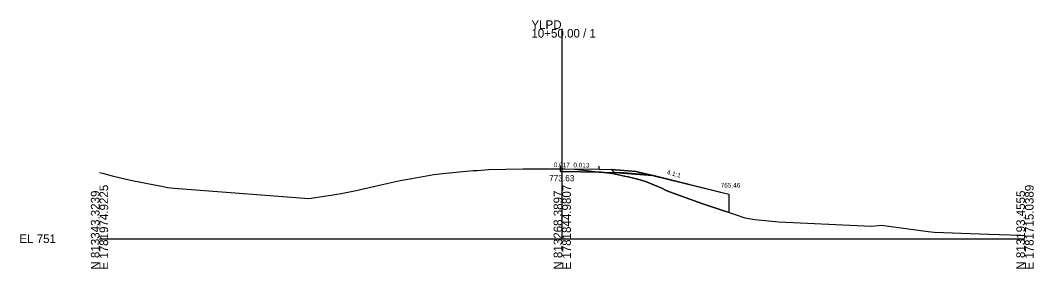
# Model space of a CAD drawing. Extents: x -26 to 353, y -10 to 9080.
# Drawn here: x -25.7 to 302.8, y 490.3 to 570.7 of the extents above; entities that cross this region are included whole.
import ezdxf

# ---------------------------------------------------------------- set-up
doc = ezdxf.new("R2010")
doc.units = 0
for name, color, linetype in [('Exist Cross Section Cell', 7, 'Continuous'), ('Exist XS Center Line Elevation Label', 7, 'Continuous'), ('Exist XS Ground Line', 7, 'Continuous'), ('Prop XS Ditch Standard Text', 7, 'Continuous'), ('Prop XS Dump Level', 7, 'Continuous'), ('Prop XS Earthwork Shape', 7, 'Continuous'), ('Prop XS EOT Tick Mark', 7, 'Continuous'), ('Prop XS Finish Grade', 7, 'Continuous'), ('Prop XS Finish Grade Earthwork', 7, 'Continuous'), ('Prop XS Finish Grade Paved Shoulder', 7, 'Continuous'), ('Prop XS Finish Grade Pavement', 7, 'Continuous'), ('Prop XS Pvmt Edge Slope', 7, 'Continuous'), ('Prop XS SE Text', 7, 'Continuous'), ('Prop XS Side Slope Text', 7, 'Continuous'), ('Prop XS Subgrade Earthwork', 7, 'Continuous'), ('Scratch_Level_3', 7, 'Continuous')]:
    doc.layers.add(name, color=color, linetype=linetype)

msp = doc.modelspace()

# ---------------------------------------------------------------- linework, layer by layer
at = {"layer": 'Exist Cross Section Cell'}
for p, q in [((150, 500), (150, 567.93)), ((0, 500), (150, 500)), ((150, 500), (300, 500))]:
    msp.add_line(p, q, dxfattribs=at)
at = {"layer": 'Exist XS Ground Line'}
for p, q in [((122.5, 522.15), (126.08, 522.41)), ((126.08, 522.41), (137.36, 522.61)), ((137.36, 522.61), (137.76, 522.61)), ((137.76, 522.61), (149.46, 522.64)), ((149.46, 522.64), (150, 522.63)), ((150, 522.63), (150.91, 522.61)), ((150.91, 522.61), (154.01, 522.53)), ((154.01, 522.53), (155.04, 522.41)), ((155.04, 522.41), (166.27, 521.16)), ((0, 521.43), (0.94, 521.2)), ((0.94, 521.2), (4.12, 520.41)), ((4.12, 520.41), (9.99, 518.99)), ((97.45, 518.87), (101.23, 519.52)), ((101.23, 519.52), (108.33, 520.8)), ((108.33, 520.8), (111.16, 521.13)), ((111.16, 521.13), (121.15, 522.05)), ((121.15, 522.05), (122.5, 522.15)), ((166.27, 521.16), (170.16, 520.27)), ((170.16, 520.27), (171.36, 520.01)), ((171.36, 520.01), (175.25, 519.07)), ((9.99, 518.99), (18.41, 517.3)), ((18.41, 517.3), (21.12, 516.82)), ((21.12, 516.82), (22.03, 516.56)), ((22.03, 516.56), (24.17, 516.34)), ((24.17, 516.34), (28.36, 516.11)), ((28.36, 516.11), (67.86, 513.05)), ((83.23, 515.66), (93.58, 517.95)), ((93.58, 517.95), (97.45, 518.87)), ((175.25, 519.07), (177.32, 518.47)), ((177.32, 518.47), (182.48, 516.22)), ((182.48, 516.22), (183.48, 515.78)), ((67.86, 513.05), (73.53, 513.85)), ((73.53, 513.85), (78.28, 514.63)), ((78.28, 514.63), (83.23, 515.66)), ((183.48, 515.78), (184.82, 515.23)), ((184.82, 515.23), (195.3, 511.44)), ((195.3, 511.44), (200.1, 509.81)), ((200.1, 509.81), (206.05, 507.84)), ((206.05, 507.84), (209.15, 506.75)), ((209.15, 506.75), (212.39, 506.26)), ((212.39, 506.26), (220.26, 505.44)), ((220.26, 505.44), (250.3, 504.13)), ((250.3, 504.13), (253.44, 504.35)), ((253.44, 504.35), (268.66, 502.34)), ((268.66, 502.34), (270.58, 502.14)), ((270.58, 502.14), (273.6, 502.01)), ((273.6, 502.01), (288.18, 501.44)), ((288.18, 501.44), (298.65, 501.13)), ((298.65, 501.13), (300, 501.11))]:
    msp.add_line(p, q, dxfattribs=at)
at = {"layer": 'Prop XS Dump Level'}
for p, q in [((149.45, 522.67), (150, 522.66)), ((150, 522.66), (162, 522.5))]:
    msp.add_line(p, q, dxfattribs=at)
at = {"layer": 'Prop XS Earthwork Shape'}
for points in [[(149.45, 521.76), (149.45, 522.64), (150, 522.63), (150.91, 522.61), (154.01, 522.53), (155.04, 522.41), (162.55, 521.58), (161.98, 521.59), (149.99, 521.75)], [(204.04, 514.46), (204.04, 508.5), (200.1, 509.81), (195.3, 511.44), (184.82, 515.23), (183.48, 515.78), (182.48, 516.22), (177.32, 518.47), (175.25, 519.07), (171.36, 520.01), (170.16, 520.27), (166.27, 521.16), (162.55, 521.58), (169.85, 521.43), (179.08, 520.69)]]:
    msp.add_lwpolyline(points, close=True, dxfattribs=at)
at = {"layer": 'Prop XS EOT Tick Mark'}
for p, q in [((149.45, 522.67), (149.45, 523.67)), ((162, 522.5), (162, 523.5))]:
    msp.add_line(p, q, dxfattribs=at)
at = {"layer": 'Prop XS Finish Grade'}
for p, q in [((166, 522.42), (174, 521.78)), ((174, 521.78), (179.26, 520.5))]:
    msp.add_line(p, q, dxfattribs=at)
at = {"layer": 'Prop XS Finish Grade Earthwork'}
for p, q in [((179.26, 520.5), (204.04, 514.46)), ((204.04, 514.46), (204.04, 508.5))]:
    msp.add_line(p, q, dxfattribs=at)
at = {"layer": 'Prop XS Finish Grade Paved Shoulder'}
msp.add_line((162, 522.5), (166, 522.42), dxfattribs=at)
at = {"layer": 'Prop XS Finish Grade Pavement'}
for p, q in [((149.45, 522.67), (150, 522.66)), ((150, 522.66), (162, 522.5))]:
    msp.add_line(p, q, dxfattribs=at)
at = {"layer": 'Prop XS Pvmt Edge Slope'}
msp.add_line((166, 522.42), (166.94, 521.49), dxfattribs=at)
at = {"layer": 'Prop XS Subgrade Earthwork'}
for p, q in [((149.45, 521.76), (149.45, 522.64)), ((149.45, 521.76), (149.99, 521.75)), ((149.99, 521.75), (161.98, 521.59)), ((161.98, 521.59), (166.94, 521.49)), ((166.94, 521.49), (179.26, 520.5))]:
    msp.add_line(p, q, dxfattribs=at)
at = {"layer": 'Scratch_Level_3'}
for p, q in [((174, 521.78), (166, 522.42)), ((166, 522.42), (166.94, 521.49)), ((166.94, 521.49), (179.26, 520.5)), ((179.26, 520.5), (174, 521.78))]:
    msp.add_line(p, q, dxfattribs=at)

# ---------------------------------------------------------------- texts
at = {"layer": 'Exist Cross Section Cell'}
for s, p in [('YLPD', (140, 567.93)), ('10+50.00 / 1', (140, 565.13)), ('EL 751', (-26, 498.6))]:
    msp.add_text(s, height=2.8, dxfattribs=at).set_placement(p)
for s, p in [('E 1781974.9225', (2.8, 490)), ('E 1781844.9807', (152.8, 490)), ('E 1781715.0389', (302.8, 490)), ('N 813343.3239', (0, 490)), ('N 813268.3897', (150, 490)), ('N 813193.4555', (300, 490))]:
    msp.add_text(s, height=2.8, rotation=90, dxfattribs=at).set_placement(p)
at = {"layer": 'Exist XS Center Line Elevation Label'}
msp.add_text('773.63', height=2, dxfattribs=at).set_placement((145.75, 518.63))
at = {"layer": 'Prop XS Ditch Standard Text'}
msp.add_text('765.46', height=1.5, dxfattribs=at).set_placement((201.37, 516.56))
at = {"layer": 'Prop XS Dump Level'}
msp.add_text('Case4', height=0.04, dxfattribs=at).set_placement((174, 521.99))
at = {"layer": 'Prop XS SE Text'}
for s, rotation, p in [('0.017', 359.044, (147.27, 523.21)), ('0.013', 359.2346, (153.59, 523.12))]:
    msp.add_text(s, height=1.5, rotation=rotation, dxfattribs=at).set_placement(p)
at = {"layer": 'Prop XS Side Slope Text'}
msp.add_text('4.1:1', height=1.5, rotation=345.9638, dxfattribs=at).set_placement((183.77, 520.87))

doc.saveas('drawing.dxf')
